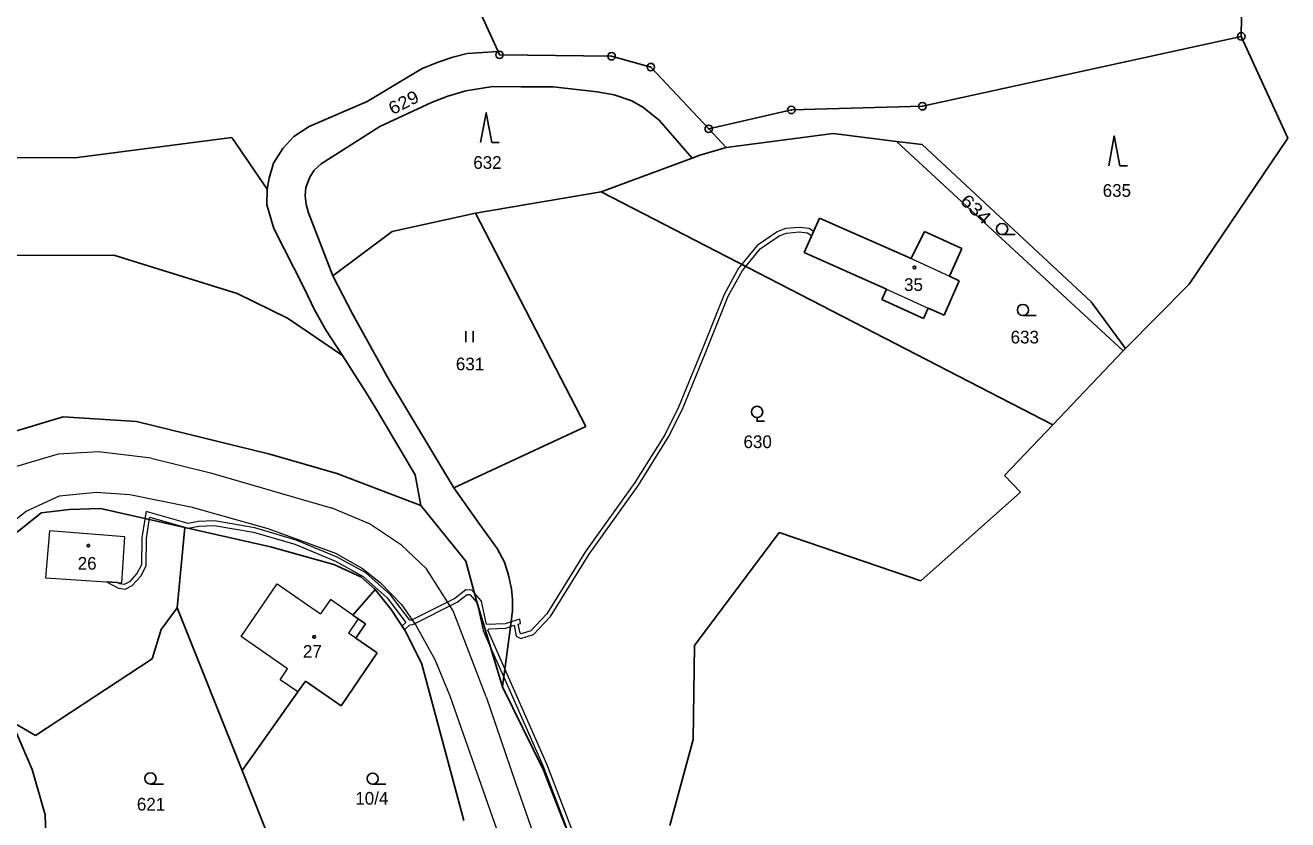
# Model space of a CAD drawing. Extents: x -653193 to -651624, y -1092017 to -1090260.
# Drawn here: x -653007.1 to -652838, y -1091143 to -1091036.5 of the extents above; entities that cross this region are included whole.
import ezdxf
from ezdxf.enums import TextEntityAlignment as Align

# ---------------------------------------------------------------- set-up
doc = ezdxf.new("R2010")
doc.units = 0
doc.header["$LTSCALE"] = 0.68
for name, color, linetype, lineweight in [('1', 7, 'Continuous', 25), ('13', 7, 'Continuous', 13), ('3', 7, 'Continuous', 25), ('4', 7, 'Continuous', 13), ('5', 7, 'Continuous', 25), ('8', 7, 'Continuous', 25)]:
    doc.layers.add(name, color=color, linetype=linetype, lineweight=lineweight)
doc.layers.add('2', color=7, linetype='Continuous')

msp = doc.modelspace()

# ---------------------------------------------------------------- linework, layer by layer
at = {"layer": '1'}
for p, q in [((-652956.33, -1091012.41), (-652943.77, -1091040.03)), ((-652844.26, -1091038.01), (-652844.13, -1091029.85)), ((-652886.96, -1091047.37), (-652844.26, -1091038.01)), ((-652838.04, -1091051.64), (-652844.26, -1091038.01)), ((-652951.78, -1091041.47), (-652949.82, -1091040.78)), ((-652949.82, -1091040.78), (-652947.91, -1091040.32)), ((-652947.91, -1091040.32), (-652943.77, -1091040.03)), ((-652943.77, -1091040.03), (-652943.57, -1091040.48)), ((-652943.57, -1091040.48), (-652928.57, -1091040.67)), ((-652928.57, -1091040.67), (-652923.32, -1091042.12)), ((-652961.3, -1091046.75), (-652953.94, -1091042.33)), ((-652953.94, -1091042.33), (-652951.78, -1091041.47)), ((-652923.32, -1091042.12), (-652915.56, -1091050.4)), ((-652952.69, -1091046.87), (-652950.51, -1091046)), ((-652950.51, -1091046), (-652948.08, -1091045.3)), ((-652948.08, -1091045.3), (-652944.48, -1091044.72)), ((-652940.73, -1091044.78), (-652944.48, -1091044.72)), ((-652940.73, -1091044.78), (-652936.39, -1091044.77)), ((-652936.39, -1091044.77), (-652930.49, -1091045.44)), ((-652930.49, -1091045.44), (-652928.21, -1091045.86)), ((-652928.21, -1091045.86), (-652925.85, -1091046.66)), ((-652969.06, -1091050.1), (-652961.3, -1091046.75)), ((-652959.6, -1091050.09), (-652952.69, -1091046.87)), ((-652925.85, -1091046.66), (-652924.39, -1091047.48)), ((-652924.39, -1091047.48), (-652922.2, -1091049.22)), ((-652915.56, -1091050.4), (-652904.5, -1091047.86)), ((-652904.5, -1091047.86), (-652886.96, -1091047.37)), ((-652922.2, -1091049.22), (-652917.78, -1091054.31)), ((-652972.6, -1091053.01), (-652971.09, -1091051.4)), ((-652971.09, -1091051.4), (-652969.06, -1091050.1)), ((-652967.45, -1091055.1), (-652959.6, -1091050.09)), ((-652913.24, -1091052.9), (-652915.56, -1091050.4)), ((-652913.24, -1091052.9), (-652898.91, -1091051.03)), ((-652898.91, -1091051.03), (-652890.44, -1091052.08)), ((-653000.41, -1091054.28), (-652979.41, -1091051.55)), ((-652973.83, -1091055), (-652972.6, -1091053.01)), ((-652916.77, -1091053.92), (-652913.24, -1091052.9)), ((-652890.44, -1091052.08), (-652886.99, -1091052.51)), ((-652860.08, -1091080.13), (-652890.44, -1091052.08)), ((-652886.99, -1091052.51), (-652864.35, -1091073.56)), ((-652851.24, -1091071.19), (-652838.04, -1091051.64)), ((-653016.89, -1091054.24), (-653000.41, -1091054.28)), ((-652917.78, -1091054.31), (-652929.98, -1091058.83)), ((-652917.78, -1091054.31), (-652916.77, -1091053.92)), ((-652974.41, -1091056.99), (-652973.83, -1091055)), ((-652968.97, -1091056.86), (-652968.38, -1091055.95)), ((-652968.38, -1091055.95), (-652967.45, -1091055.1)), ((-652969.51, -1091058.26), (-652969.3, -1091057.66)), ((-652969.3, -1091057.66), (-652968.97, -1091056.86)), ((-652974.69, -1091058.49), (-652974.72, -1091060.59)), ((-652969.59, -1091059.32), (-652969.51, -1091058.26)), ((-652969.44, -1091060.53), (-652969.59, -1091059.32)), ((-652929.98, -1091058.83), (-652946.81, -1091061.71)), ((-652869.49, -1091090.03), (-652929.98, -1091058.83)), ((-652974.72, -1091060.59), (-652973.79, -1091063.73)), ((-652969.13, -1091061.65), (-652969.44, -1091060.53)), ((-652965.88, -1091070.1), (-652969.13, -1091061.65)), ((-652946.81, -1091061.71), (-652957.93, -1091064.17)), ((-652932.02, -1091090.29), (-652946.81, -1091061.71)), ((-652902.78, -1091066.94), (-652900.73, -1091062.38)), ((-652900.73, -1091062.38), (-652888.45, -1091067.76)), ((-652973.79, -1091063.73), (-652969.68, -1091071.82)), ((-652957.93, -1091064.17), (-652965.88, -1091070.1)), ((-652888.45, -1091067.76), (-652886.68, -1091064.17)), ((-652886.68, -1091064.17), (-652881.67, -1091066.43)), ((-652881.67, -1091066.43), (-652883.34, -1091070.13)), ((-653017.28, -1091067.36), (-652995.19, -1091067.3)), ((-652995.19, -1091067.3), (-652978.7, -1091072.46)), ((-652902.78, -1091066.94), (-652891.74, -1091071.89)), ((-652965.88, -1091070.1), (-652963.21, -1091075.28)), ((-652882.04, -1091070.74), (-652884.04, -1091075.36)), ((-652883.34, -1091070.13), (-652882.04, -1091070.74)), ((-652859.77, -1091079.81), (-652851.24, -1091071.19)), ((-652978.7, -1091072.46), (-652971.95, -1091075.78)), ((-652969.68, -1091071.82), (-652968.33, -1091074.63)), ((-652892.37, -1091073.28), (-652891.74, -1091071.89)), ((-652886.8, -1091075.79), (-652892.37, -1091073.28)), ((-652968.33, -1091074.63), (-652966.79, -1091077.39)), ((-652886.17, -1091074.4), (-652886.8, -1091075.79)), ((-652884.04, -1091075.36), (-652886.17, -1091074.4)), ((-652864.35, -1091073.56), (-652859.77, -1091079.81)), ((-652971.95, -1091075.78), (-652964.61, -1091080.77)), ((-652963.21, -1091075.28), (-652958.37, -1091083.99)), ((-652966.79, -1091077.39), (-652964.61, -1091080.77)), ((-652860.08, -1091080.13), (-652869.49, -1091090.03)), ((-652859.77, -1091079.81), (-652860.08, -1091080.13)), ((-652964.61, -1091080.77), (-652961.37, -1091085.8)), ((-652958.37, -1091083.99), (-652949.71, -1091098.47)), ((-652961.37, -1091085.8), (-652960.06, -1091087.99)), ((-652960.06, -1091087.99), (-652954.86, -1091096.73)), ((-653009.73, -1091091.28), (-653001.98, -1091088.96)), ((-653001.98, -1091088.96), (-652992.16, -1091089.62)), ((-652992.16, -1091089.62), (-652974.34, -1091093.97)), ((-652949.71, -1091098.47), (-652932.02, -1091090.29)), ((-652869.49, -1091090.03), (-652875.97, -1091096.83)), ((-652974.34, -1091093.97), (-652965.36, -1091096.57)), ((-652965.36, -1091096.57), (-652954.09, -1091100.85)), ((-652954.86, -1091096.73), (-652954.09, -1091100.85)), ((-652875.97, -1091096.83), (-652873.81, -1091099.08)), ((-652946.33, -1091103.23), (-652949.71, -1091098.47)), ((-652873.81, -1091099.08), (-652887.16, -1091110.95)), ((-653004.94, -1091101.86), (-653008.17, -1091104.44)), ((-653001.14, -1091101.39), (-653004.94, -1091101.86)), ((-652996.98, -1091101.25), (-653001.14, -1091101.39)), ((-652985.72, -1091103.79), (-652996.98, -1091101.25)), ((-652954.09, -1091100.85), (-652948.07, -1091108.3)), ((-652985.72, -1091103.79), (-652986.73, -1091114.55)), ((-652974.24, -1091106.41), (-652985.72, -1091103.79)), ((-652943.89, -1091106.64), (-652946.33, -1091103.23)), ((-652906.15, -1091104.46), (-652917.48, -1091119.62)), ((-652887.16, -1091110.95), (-652906.15, -1091104.46)), ((-652965.77, -1091108.76), (-652974.24, -1091106.41)), ((-652942.91, -1091108.44), (-652943.89, -1091106.64)), ((-652962.15, -1091110.42), (-652965.77, -1091108.76)), ((-652948.07, -1091108.3), (-652946.66, -1091113.64)), ((-652942.36, -1091110.17), (-652942.91, -1091108.44)), ((-652941.98, -1091112.04), (-652942.36, -1091110.17)), ((-652963.19, -1091115.55), (-652960.22, -1091112.11)), ((-652941.83, -1091113.46), (-652941.98, -1091112.04)), ((-652946.66, -1091113.64), (-652943.18, -1091125.14)), ((-652941.85, -1091114.91), (-652941.83, -1091113.46)), ((-652988.86, -1091117.48), (-652986.73, -1091114.55)), ((-652978.03, -1091136.35), (-652986.73, -1091114.55)), ((-652963.19, -1091115.55), (-652962.49, -1091116.04)), ((-652942, -1091116.44), (-652941.85, -1091114.91)), ((-652961.5, -1091116.72), (-652962.81, -1091118.63)), ((-652962.49, -1091116.04), (-652961.5, -1091116.72)), ((-652943.18, -1091125.14), (-652942, -1091116.44)), ((-652990.06, -1091121.42), (-652988.86, -1091117.48)), ((-652962.81, -1091118.63), (-652959.96, -1091120.6)), ((-652953.97, -1091122.11), (-652956.1, -1091117.79)), ((-652959.96, -1091120.6), (-652964.78, -1091127.68)), ((-652917.48, -1091119.62), (-652917.65, -1091132.22)), ((-652990.06, -1091121.42), (-653005.69, -1091131.68)), ((-652948.33, -1091143.08), (-652953.97, -1091122.11)), ((-652969.56, -1091124.37), (-652970.58, -1091125.84)), ((-652964.78, -1091127.68), (-652969.56, -1091124.37)), ((-652943.18, -1091125.14), (-652937.69, -1091136.31)), ((-652970.58, -1091125.84), (-652978.03, -1091136.35)), ((-652917.65, -1091132.22), (-652920.79, -1091143.71)), ((-653006.14, -1091136.24), (-653004.4, -1091142.31)), ((-652971.95, -1091151.58), (-652978.03, -1091136.35)), ((-652937.69, -1091136.31), (-652935.16, -1091142.84)), ((-653004.4, -1091142.31), (-653004.16, -1091149.98)), ((-652935.16, -1091142.84), (-652931.98, -1091150.63))]:
    msp.add_line(p, q, dxfattribs=at)
for points in [[(-652979.41, -1091051.55), (-652974.69, -1091058.49), (-652974.41, -1091056.99)], [(-652956.1, -1091117.79), (-652958.07, -1091114.77), (-652960.22, -1091112.11), (-652962.15, -1091110.42)], [(-653005.69, -1091131.68), (-653008.93, -1091129.81), (-653006.14, -1091136.24)]]:
    msp.add_lwpolyline(points, dxfattribs=at)
at = {"layer": '13'}
for points in [[(-652901.78, -1091064.71), (-652901.53, -1091064.15), (-652902.11, -1091063.76), (-652903.45, -1091063.6), (-652905.29, -1091063.76), (-652906.39, -1091064.18), (-652909.07, -1091066.02), (-652911.14, -1091068.54), (-652910.6, -1091068.83), (-652908.67, -1091066.46), (-652906.11, -1091064.72), (-652905.15, -1091064.36), (-652903.45, -1091064.2), (-652902.33, -1091064.34)], [(-652912.95, -1091072.83), (-652911.06, -1091069.39), (-652910.6, -1091068.83), (-652911.14, -1091068.54), (-652911.56, -1091069.05), (-652913.49, -1091072.57), (-652916.55, -1091080.18), (-652919.6, -1091087.7), (-652921.45, -1091091.37), (-652925.45, -1091097.78), (-652932.08, -1091107.03), (-652937.23, -1091115.37), (-652939.36, -1091117.63), (-652940.67, -1091118.05), (-652940.82, -1091117.96), (-652941.09, -1091116.75), (-652940.75, -1091116.68), (-652940.85, -1091116.08), (-652942, -1091116.44), (-652942.09, -1091117.07), (-652941.62, -1091116.9), (-652941.36, -1091118.36), (-652940.73, -1091118.69), (-652939.02, -1091118.15), (-652936.75, -1091115.73), (-652931.58, -1091107.37), (-652924.95, -1091098.12), (-652920.93, -1091091.67), (-652919.06, -1091087.94), (-652915.99, -1091080.4)], [(-652991.04, -1091102.59), (-652990.46, -1091102.72), (-652990.41, -1091102.42), (-652985.28, -1091103.9), (-652983.82, -1091103.61), (-652981.76, -1091103.53), (-652976.49, -1091104.45), (-652970.99, -1091106.04), (-652965.55, -1091108.31), (-652961.81, -1091110.39), (-652958.63, -1091113.22), (-652956.12, -1091116.53), (-652956.62, -1091117), (-652956.29, -1091117.5), (-652955.59, -1091116.85), (-652955.18, -1091116.8), (-652949.24, -1091113.83), (-652947.89, -1091112.79), (-652947.55, -1091112.8), (-652946.58, -1091113.91), (-652946.66, -1091113.64), (-652946.94, -1091112.6), (-652947.27, -1091112.22), (-652948.09, -1091112.17), (-652949.56, -1091113.31), (-652955.36, -1091116.22), (-652955.58, -1091116.24), (-652958.19, -1091112.82), (-652961.47, -1091109.89), (-652965.29, -1091107.77), (-652970.79, -1091105.48), (-652976.35, -1091103.87), (-652981.72, -1091102.93), (-652983.9, -1091103.01), (-652985.26, -1091103.28), (-652990.89, -1091101.66)], [(-652991.45, -1091105.18), (-652991.49, -1091108.79), (-652992.11, -1091109.98), (-652993.12, -1091111.1), (-652993.81, -1091111.44), (-652994.41, -1091111.37), (-652994.78, -1091111.17), (-652996.21, -1091111.08), (-652994.59, -1091111.95), (-652993.71, -1091112.06), (-652992.76, -1091111.58), (-652991.61, -1091110.32), (-652990.89, -1091108.93), (-652990.85, -1091105.24), (-652990.48, -1091102.86), (-652990.46, -1091102.72), (-652991.04, -1091102.59), (-652991.06, -1091102.71)], [(-652945.13, -1091117.58), (-652944.97, -1091117.38), (-652942.71, -1091117.3), (-652942.09, -1091117.07), (-652942, -1091116.44), (-652942.83, -1091116.7), (-652945.33, -1091116.8), (-652945.99, -1091113.66), (-652946.94, -1091112.6), (-652946.66, -1091113.64), (-652946.58, -1091113.91), (-652946.55, -1091113.94), (-652946.51, -1091114.15), (-652944.77, -1091119.88), (-652943.01, -1091123.87), (-652942.85, -1091122.73)], [(-652945.77, -1091117.62), (-652944.77, -1091119.88), (-652946.51, -1091114.15)], [(-652937.22, -1091135.49), (-652942.85, -1091122.73), (-652943.01, -1091123.87), (-652937.78, -1091135.71), (-652933.58, -1091146.72), (-652931.98, -1091150.63), (-652931.53, -1091150.4)]]:
    msp.add_lwpolyline(points, close=True, dxfattribs=at)
at = {"layer": '3'}
for p, q in [((-652944.6, -1091052.24), (-652943.604, -1091052.24)), ((-652860.51, -1091055.34), (-652859.514, -1091055.34)), ((-652876.283, -1091064.56), (-652874.533, -1091064.56)), ((-652873.493, -1091075.41), (-652871.743, -1091075.41)), ((-652948.081, -1091078.98), (-652948.081, -1091077.48)), ((-652947.08, -1091078.98), (-652947.08, -1091077.48)), ((-652990.313, -1091138.18), (-652988.563, -1091138.18)), ((-652960.553, -1091138.2), (-652958.803, -1091138.2))]:
    msp.add_line(p, q, dxfattribs=at)
for points in [[(-652944.6, -1091052.24), (-652945.35, -1091048.24), (-652946.1, -1091052.24)], [(-652860.51, -1091055.34), (-652861.26, -1091051.34), (-652862.01, -1091055.34)], [(-652909.08, -1091089.072), (-652909.08, -1091089.57), (-652908.079, -1091089.57)]]:
    msp.add_lwpolyline(points, dxfattribs=at)
for centre in [(-652876.2829, -1091063.8098), (-652873.4929, -1091074.6598), (-652909.0793, -1091088.3209), (-652990.3129, -1091137.4298), (-652960.5529, -1091137.4498)]:
    msp.add_circle(centre, 0.75, dxfattribs=at)
at = {"layer": '4'}
for p, q in [((-652888.45, -1091067.76), (-652883.34, -1091070.13)), ((-652891.74, -1091071.89), (-652886.17, -1091074.4)), ((-652997.25, -1091093.67), (-653002.66, -1091093.97)), ((-652990.21, -1091094.53), (-652997.25, -1091093.67)), ((-653002.66, -1091093.97), (-653008.25, -1091095.61)), ((-652990.21, -1091094.53), (-652982.28, -1091096.5)), ((-652982.28, -1091096.5), (-652966, -1091101.21)), ((-653006.96, -1091101.6), (-653002.5, -1091099.57)), ((-653002.5, -1091099.57), (-652997.56, -1091099.08)), ((-652997.56, -1091099.08), (-652993.06, -1091099.37)), ((-652993.06, -1091099.37), (-652984.91, -1091101.04)), ((-653010.08, -1091104.07), (-653006.96, -1091101.6)), ((-652984.91, -1091101.04), (-652974.6, -1091103.96)), ((-652961, -1091103.3), (-652966, -1091101.21)), ((-652956.7, -1091106.16), (-652961, -1091103.3)), ((-653003.84, -1091104.27), (-653004.36, -1091110.56)), ((-652993.75, -1091105.04), (-653003.84, -1091104.27)), ((-652994.15, -1091111.21), (-652993.75, -1091105.04)), ((-652974.6, -1091103.96), (-652965.52, -1091107.23)), ((-652965.52, -1091107.23), (-652961.92, -1091109.31)), ((-652953.35, -1091109.32), (-652956.7, -1091106.16)), ((-653004.36, -1091110.56), (-652994.15, -1091111.21)), ((-652961.92, -1091109.31), (-652959.54, -1091111.19)), ((-652949.79, -1091114.95), (-652953.35, -1091109.32)), ((-652959.54, -1091111.19), (-652956.71, -1091114.12)), ((-652956.71, -1091114.12), (-652954.76, -1091116.89)), ((-652945.38, -1091126.47), (-652949.79, -1091114.95)), ((-652962.49, -1091116.04), (-652963.78, -1091117.95)), ((-652954.76, -1091116.89), (-652952.22, -1091121.48)), ((-652971.94, -1091122.73), (-652978.14, -1091118.41)), ((-652962.81, -1091118.63), (-652963.78, -1091117.95)), ((-652952.22, -1091121.48), (-652950.21, -1091126.37)), ((-652972.96, -1091124.2), (-652971.94, -1091122.73)), ((-652970.58, -1091125.84), (-652972.96, -1091124.2)), ((-652950.21, -1091126.37), (-652940.46, -1091154.27)), ((-652945.38, -1091126.47), (-652941.43, -1091138.03)), ((-652941.43, -1091138.03), (-652931.98, -1091165.22))]:
    msp.add_line(p, q, dxfattribs=at)
for points in [[(-652978.14, -1091118.41), (-652973.32, -1091111.35), (-652967.52, -1091115.37)], [(-652963.19, -1091115.55), (-652966.21, -1091113.47), (-652967.52, -1091115.37)]]:
    msp.add_lwpolyline(points, dxfattribs=at)
at = {"layer": '5'}
for centre in [(-652888.0068, -1091068.9792), (-652998.6168, -1091106.2292), (-652968.3768, -1091118.4592)]:
    msp.add_circle(centre, 0.175, dxfattribs=at)
at = {"layer": '8'}
for centre, radius in [((-652844.26, -1091038.0099), 0.5), ((-652844.26, -1091038.0099), 0.0303), ((-652943.57, -1091040.4799), 0.5), ((-652943.57, -1091040.4799), 0.0303), ((-652928.57, -1091040.6699), 0.5), ((-652928.57, -1091040.6699), 0.0303), ((-652923.32, -1091042.1199), 0.5), ((-652923.32, -1091042.1199), 0.0303), ((-652904.5, -1091047.8599), 0.5), ((-652904.5, -1091047.8599), 0.0303), ((-652886.96, -1091047.3699), 0.5), ((-652886.96, -1091047.3699), 0.0303), ((-652915.56, -1091050.3999), 0.5), ((-652915.56, -1091050.3999), 0.0303)]:
    msp.add_circle(centre, radius, dxfattribs=at)

# ---------------------------------------------------------------- texts
at = {"layer": '2'}
for s, rotation, width, p in [('629', 27, 1.1, (-652956.0294, -1091047.6183)), ('634', 317, 1.2, (-652880.3737, -1091061.776))]:
    msp.add_text(s, height=1.7, rotation=rotation, dxfattribs=dict(at, width=width)).set_placement(p, align=Align.CENTER)
for s, p in [('632', (-652945.189, -1091055.755)), ('635', (-652860.919, -1091059.505)), ('35', (-652888.149, -1091072.115)), ('633', (-652873.249, -1091079.145)), ('631', (-652947.519, -1091082.745)), ('630', (-652909.009, -1091093.165)), ('26', (-652998.779, -1091109.455)), ('27', (-652968.629, -1091121.255)), ('10/4', (-652960.669, -1091140.935)), ('621', (-652990.229, -1091141.725))]:
    msp.add_text(s, height=1.7, dxfattribs=at).set_placement(p, align=Align.CENTER)

doc.saveas('drawing.dxf')
